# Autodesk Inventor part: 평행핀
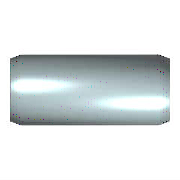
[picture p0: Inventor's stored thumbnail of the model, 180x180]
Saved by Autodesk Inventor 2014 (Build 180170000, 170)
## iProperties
IsCustomPart: 0
Created: 2009-02
Part Number: 평행핀
Material: 강, 연강
Description: 평행 핀
Document SubType Name: Modeling
Standard: KS B 1320
Designer: KYOUNG IL JANG
Standards Organization: KS
Language: ko-KR
Size Designation: B 5 x  20
Categories: <MemberInstance><Categories><Category DisplayName="조임쇠" InternalName="e4da775c-781d-43d5-af7c-5136215cf5a6" Mnemonic="FSTN"><Category DisplayName="핀" InternalNa
Density: 7.86 g/cm^3
Appearance: 강철
Mass: 3.06605 g
Surface Area: 3.46755 cm^2
Volume: 0.390082 cm^3
Author: KYOUNG IL JANG
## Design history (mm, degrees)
sketch "스케치"
  geometry: C1 r 2.5 at (0, 0); 1 further point
  constraints: 1 centre point, 1 coincident
  dimensions: "d1" = 5 diameter of C1 (= NND)
extrude "본체" new body sketch "스케치" distance "d2" = 20 (= NLG); taper "d3" = 0 deg
chamfer "스케치2" distance "d8" = 0.8 (= PHH); stored, may be unused: angle "d9" = 15 deg (= FAWI), second distance "d12" = 0.8 (= PHH)
body "Solid1"
chamfer "모따기1" distance "d4" = 0.8 (= PHH); stored, may be unused: angle "d5" = 15 deg (= FAWI), second distance "d11" = 0.8 (= PHH)
other parameters: "NND" = 5 [user parameter; used in 1 equation term], "NLG" = 20 [user parameter; used in 1 equation term], "PHH" = 0.8 [user parameter; used in 4 equation terms], "FAWI" = 15 deg [user parameter; used in 2 equation terms], "d13" = 0, "d15" = 0, "d16" = 0, "KAH" = 0.63 [user parameter]
